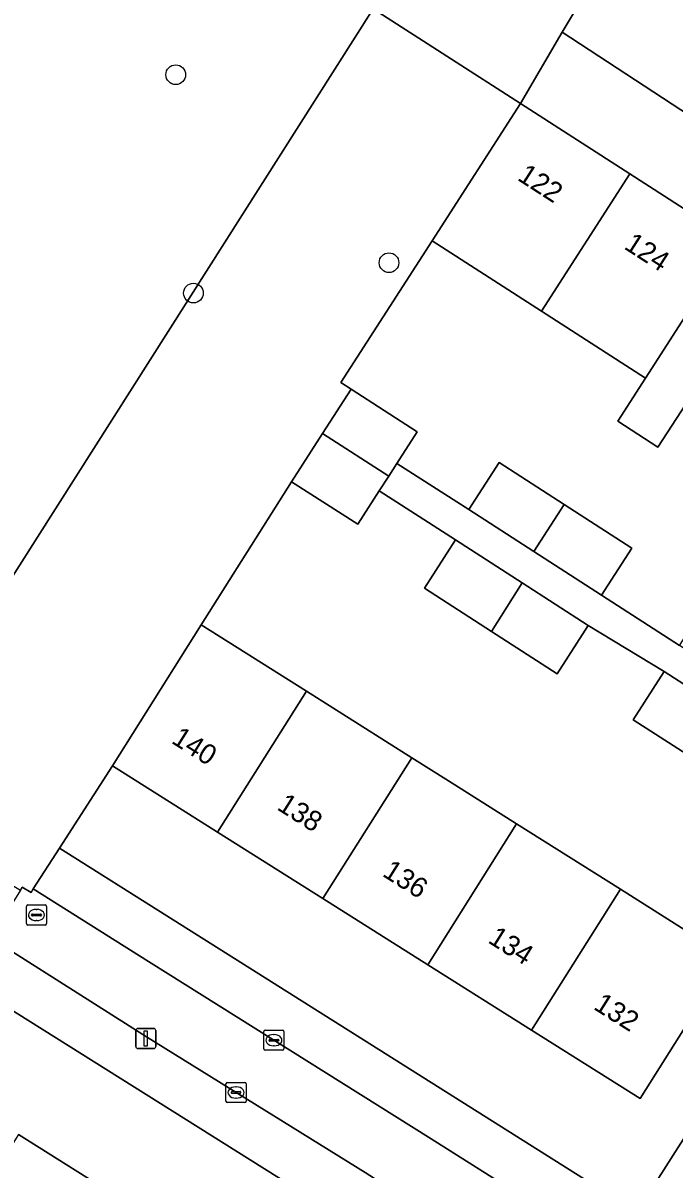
# Model space of a CAD drawing. Extents: x 159039 to 160102, y 381214 to 382524.
# Drawn here: x 159305.6 to 159337.9, y 381849 to 381905.9 of the extents above; entities that cross this region are included whole.
import ezdxf

# ---------------------------------------------------------------- set-up
doc = ezdxf.new("R2010")
doc.units = 0
for name, color, linetype in [('IMGEO_Boom', 7, 'Continuous'), ('IMGEO_Erf', 7, 'Continuous'), ('IMGEO_Groenvoorziening', 7, 'Continuous'), ('IMGEO_Kolk', 7, 'Continuous'), ('IMGEO_Lichtmast', 7, 'Continuous'), ('IMGEO_Pand', 7, 'Continuous'), ('IMGEO_Pand_nummerreeks', 7, 'Continuous'), ('IMGEO_Rijbaan_lokaal_open', 7, 'Continuous'), ('IMGEO_Rioolput', 7, 'Continuous'), ('IMGEO_Voetpad_open', 7, 'Continuous')]:
    doc.layers.add(name, color=color, linetype=linetype)

msp = doc.modelspace()

# ---------------------------------------------------------------- linework, layer by layer
at = {"layer": 'IMGEO_Boom'}
for centre in [(159313.176, 381903.321), (159323.769, 381893.982), (159314.057, 381892.471)]:
    msp.add_circle(centre, 0.489, dxfattribs=at)
at = {"layer": 'IMGEO_Erf'}
for points in [[(159359.86, 381887.675), (159359.727, 381887.759), (159350.052, 381893.861), (159332.365, 381905.434), (159330.306, 381901.885), (159335.73, 381898.391), (159340.897, 381895.062), (159346.193, 381891.651), (159351.372, 381888.315), (159356.797, 381884.82), (159352.409, 381878.007), (159346.983, 381881.502), (159341.804, 381884.838), (159338.51, 381886.96)], [(159338.51, 381886.96), (159337.13, 381884.818), (159335.128, 381886.107), (159336.508, 381888.249), (159331.341, 381891.577), (159325.917, 381895.071), (159321.381, 381888.03), (159321.89, 381887.702), (159325.177, 381885.584), (159324.166, 381884.015), (159327.732, 381881.718), (159329.234, 381884.051), (159332.464, 381881.971), (159335.828, 381879.804), (159334.325, 381877.472), (159338.207, 381874.971), (159339.709, 381877.304), (159342.939, 381875.224), (159346.303, 381873.057), (159344.8, 381870.725), (159349.432, 381867.776), (159360.21, 381884.703)], [(159339.221, 381869.129), (159335.891, 381871.274), (159337.437, 381873.674), (159333.667, 381875.963), (159332.121, 381873.562), (159328.855, 381875.666), (159325.525, 381877.811), (159327.071, 381880.211), (159323.286, 381882.649), (159322.214, 381880.985), (159318.927, 381883.102), (159314.445, 381875.985), (159319.664, 381872.694), (159324.9, 381869.393), (159326.721, 381868.244), (159330.108, 381866.109), (159335.266, 381862.856), (159340.655, 381859.458), (159336.243, 381852.461), (159330.854, 381855.859), (159325.696, 381859.111), (159320.488, 381862.395), (159315.253, 381865.696), (159310.032, 381868.988), (159307.398, 381864.904), (159336.081, 381846.809), (159348.622, 381866.504)], [(159302.409, 381834.215), (159305.789, 381832.086), (159304.31, 381829.739), (159308.104, 381827.348), (159309.583, 381829.695), (159312.83, 381827.649), (159316.21, 381825.52), (159314.731, 381823.173), (159319.263, 381820.297), (159331.792, 381840.041), (159302.646, 381858.346)], [(159305.367, 381850.678), (159310.675, 381847.333), (159315.912, 381844.034), (159321.096, 381840.767), (159326.554, 381837.328), (159322.241, 381830.483), (159316.783, 381833.922), (159313.597, 381835.929), (159312.802, 381834.667), (159312.977, 381834.557), (159311.178, 381831.701), (159309.005, 381833.071), (159311.599, 381837.188), (159306.362, 381840.488), (159301.054, 381843.832)]]:
    msp.add_lwpolyline(points, dxfattribs=at)
at = {"layer": 'IMGEO_Groenvoorziening'}
for points in [[(159322.99, 381906.598), (159330.306, 381901.885), (159332.365, 381905.434), (159334.129, 381908.375), (159336.542, 381906.753)], [(159291.155, 381871.456), (159298.019, 381867.309), (159322.99, 381906.598)]]:
    msp.add_lwpolyline(points, dxfattribs=at)
msp.add_lwpolyline([(159318.927, 381883.102), (159320.467, 381885.492), (159321.89, 381887.702), (159321.381, 381888.03), (159325.917, 381895.071), (159330.306, 381901.885), (159322.99, 381906.598), (159298.019, 381867.309), (159305.459, 381862.815), (159305.548, 381862.956), (159305.988, 381862.692), (159306.102, 381862.87), (159307.398, 381864.904), (159310.032, 381868.988), (159314.445, 381875.985)], close=True, dxfattribs=at)
at = {"layer": 'IMGEO_Kolk'}
for p, q in [((159317.552, 381854.932), (159317.552, 381855.784)), ((159317.627, 381855.858), (159318.479, 381855.858)), ((159317.811, 381855.352), (159317.811, 381855.364)), ((159318.249, 381855.315), (159317.851, 381855.315)), ((159317.854, 381855.401), (159318.252, 381855.401)), ((159318.04, 381855.638), (159318.065, 381855.638)), ((159318.295, 381855.364), (159318.295, 381855.352)), ((159318.553, 381855.784), (159318.553, 381854.932)), ((159318.479, 381854.858), (159317.627, 381854.858)), ((159318.063, 381855.078), (159318.038, 381855.078)), ((159315.672, 381852.335), (159315.672, 381853.187)), ((159315.747, 381853.261), (159316.599, 381853.261)), ((159316.16, 381853.041), (159316.185, 381853.041)), ((159316.673, 381853.187), (159316.673, 381852.335)), ((159315.931, 381852.755), (159315.931, 381852.767)), ((159316.369, 381852.718), (159315.971, 381852.718)), ((159315.974, 381852.804), (159316.372, 381852.804)), ((159316.183, 381852.481), (159316.158, 381852.481)), ((159316.415, 381852.767), (159316.415, 381852.755)), ((159316.599, 381852.261), (159315.747, 381852.261))]:
    msp.add_line(p, q, dxfattribs=at)
for points in [[(159317.552, 381854.932), (159317.552, 381855.784)], [(159317.627, 381855.858), (159318.479, 381855.858)], [(159318.553, 381855.784), (159318.553, 381854.932)], [(159318.479, 381854.858), (159317.627, 381854.858)], [(159315.672, 381852.335), (159315.672, 381853.187)], [(159315.747, 381853.261), (159316.599, 381853.261)], [(159316.673, 381853.187), (159316.673, 381852.335)], [(159316.599, 381852.261), (159315.747, 381852.261)]]:
    msp.add_lwpolyline(points, dxfattribs=at)
for centre, radius, start, end in [((159317.629, 381855.782), 0.0765, 91.552, 178.448), ((159317.629, 381855.782), 0.0765, 91.552, 178.448), ((159317.851, 381855.361), 0.0403, 85.8775, 175.7526), ((159317.848, 381855.351), 0.0366, 178.938, 274.7102), ((159318.252, 381855.358), 0.043, 264.8664, 352.4533), ((159318.256, 381855.363), 0.0386, 1.7309, 96.639), ((159318.477, 381855.782), 0.0765, 1.552, 88.448), ((159318.477, 381855.782), 0.0765, 1.552, 88.448), ((159317.629, 381854.934), 0.0765, 181.552, 268.448), ((159317.629, 381854.934), 0.0765, 181.552, 268.448), ((159318.477, 381854.934), 0.0765, 271.552, 358.448), ((159318.477, 381854.934), 0.0765, 271.552, 358.448), ((159315.749, 381853.185), 0.0765, 91.552, 178.448), ((159315.749, 381853.185), 0.0765, 91.552, 178.448), ((159316.597, 381853.185), 0.0765, 1.552, 88.448), ((159316.597, 381853.185), 0.0765, 1.552, 88.448), ((159315.971, 381852.764), 0.0403, 85.8775, 175.7526), ((159315.968, 381852.754), 0.0366, 178.938, 274.7102), ((159316.372, 381852.761), 0.043, 264.8664, 352.4533), ((159316.376, 381852.766), 0.0386, 1.7309, 96.639), ((159315.749, 381852.337), 0.0765, 181.552, 268.448), ((159315.749, 381852.337), 0.0765, 181.552, 268.448), ((159316.597, 381852.337), 0.0765, 271.552, 358.448), ((159316.597, 381852.337), 0.0765, 271.552, 358.448)]:
    msp.add_arc(centre, radius, start, end, dxfattribs=at)
for centre, major_axis, ratio, start_param, end_param in [((159318.039, 381855.358), (-0.387, 0.002), 0.722429, 4.712389, 7.853982), ((159318.064, 381855.358), (-0.39, 0.002), 0.717154, 1.570796, 4.712389), ((159316.159, 381852.761), (-0.387, 0.002), 0.722429, 4.712389, 7.853982), ((159316.184, 381852.761), (-0.39, 0.002), 0.717154, 1.570796, 4.712389)]:
    msp.add_ellipse(centre, major_axis=major_axis, ratio=ratio, start_param=start_param, end_param=end_param, dxfattribs=at)
at = {"layer": 'IMGEO_Lichtmast'}
for p, q in [((159311.295, 381855.943), (159312.085, 381855.943)), ((159312.085, 381855.943), (159311.295, 381855.943)), ((159311.195, 381855.043), (159311.195, 381855.843)), ((159311.195, 381855.843), (159311.195, 381855.043)), ((159312.185, 381855.843), (159312.185, 381855.043)), ((159312.185, 381855.043), (159312.185, 381855.843)), ((159312.085, 381854.943), (159311.295, 381854.943)), ((159311.295, 381854.943), (159312.085, 381854.943))]:
    msp.add_line(p, q, dxfattribs=at)
msp.add_lwpolyline([(159311.615, 381855.818), (159311.765, 381855.818), (159311.765, 381855.068), (159311.615, 381855.068), (159311.615, 381855.818)], dxfattribs=at)
for centre, start, end in [((159311.295, 381855.843), 90, 180), ((159311.295, 381855.843), 90, 180), ((159312.085, 381855.843), 0, 90), ((159312.085, 381855.843), 360, 90), ((159311.295, 381855.043), 180, 270), ((159311.295, 381855.043), 180, 270), ((159312.085, 381855.043), 270, 0), ((159312.085, 381855.043), 270, 0)]:
    msp.add_arc(centre, 0.1, start, end, dxfattribs=at)
at = {"layer": 'IMGEO_Pand'}
for points in [[(159335.73, 381898.391), (159330.306, 381901.885), (159325.917, 381895.071), (159331.341, 381891.577)], [(159335.73, 381898.391), (159331.341, 381891.577), (159336.508, 381888.249), (159340.897, 381895.062)], [(159346.193, 381891.651), (159340.897, 381895.062), (159336.508, 381888.249), (159335.128, 381886.107), (159337.13, 381884.818), (159338.51, 381886.96), (159341.804, 381884.838)], [(159325.177, 381885.584), (159321.89, 381887.702), (159320.467, 381885.492), (159323.754, 381883.376), (159324.166, 381884.015)], [(159323.754, 381883.376), (159320.467, 381885.492), (159318.927, 381883.102), (159322.214, 381880.985), (159323.286, 381882.649)], [(159332.464, 381881.971), (159329.234, 381884.051), (159327.732, 381881.718), (159330.961, 381879.638)], [(159332.464, 381881.971), (159330.961, 381879.638), (159334.325, 381877.472), (159335.828, 381879.804)], [(159330.378, 381878.081), (159327.071, 381880.211), (159325.525, 381877.811), (159328.855, 381875.666)], [(159330.378, 381878.081), (159328.855, 381875.666), (159332.121, 381873.562), (159333.667, 381875.963)], [(159319.664, 381872.694), (159314.445, 381875.985), (159310.032, 381868.988), (159315.253, 381865.696)], [(159340.744, 381871.544), (159337.437, 381873.674), (159335.891, 381871.274), (159339.221, 381869.129)], [(159319.664, 381872.694), (159315.253, 381865.696), (159320.488, 381862.395), (159324.9, 381869.393)], [(159330.108, 381866.109), (159326.721, 381868.244), (159324.9, 381869.393), (159320.488, 381862.395), (159325.696, 381859.111)], [(159330.108, 381866.109), (159325.696, 381859.111), (159330.854, 381855.859), (159335.266, 381862.856)], [(159335.266, 381862.856), (159330.854, 381855.859), (159336.243, 381852.461), (159340.655, 381859.458)], [(159305.367, 381850.678), (159301.054, 381843.832), (159306.362, 381840.488), (159310.675, 381847.333)]]:
    msp.add_lwpolyline(points, close=True, dxfattribs=at)
at = {"layer": 'IMGEO_Rijbaan_lokaal_open'}
msp.add_lwpolyline([(159311.827, 381859.267), (159306.102, 381862.87), (159305.988, 381862.692), (159305.548, 381862.956), (159305.459, 381862.815), (159304.189, 381860.797), (159303.964, 381860.439), (159311.727, 381855.526), (159322.579, 381848.781), (159333.091, 381842.053), (159334.772, 381844.828), (159325.861, 381850.452)], close=True, dxfattribs=at)
at = {"layer": 'IMGEO_Rioolput'}
for p, q in [((159305.759, 381861.152), (159305.759, 381862.004)), ((159305.834, 381862.078), (159306.686, 381862.078)), ((159306.018, 381861.572), (159306.018, 381861.584)), ((159306.061, 381861.621), (159306.459, 381861.621)), ((159306.247, 381861.858), (159306.272, 381861.858)), ((159306.502, 381861.584), (159306.502, 381861.572)), ((159306.76, 381862.004), (159306.76, 381861.152)), ((159306.686, 381861.078), (159305.834, 381861.078)), ((159306.456, 381861.535), (159306.058, 381861.535)), ((159306.27, 381861.298), (159306.245, 381861.298))]:
    msp.add_line(p, q, dxfattribs=at)
for points in [[(159305.759, 381861.152), (159305.759, 381862.004)], [(159305.834, 381862.078), (159306.686, 381862.078)], [(159306.76, 381862.004), (159306.76, 381861.152)], [(159306.686, 381861.078), (159305.834, 381861.078)]]:
    msp.add_lwpolyline(points, dxfattribs=at)
for centre, radius, start, end in [((159305.836, 381862.002), 0.0765, 91.552, 178.448), ((159305.836, 381862.002), 0.0765, 91.552, 178.448), ((159306.058, 381861.581), 0.0403, 85.8775, 175.7526), ((159306.055, 381861.571), 0.0366, 178.938, 274.7102), ((159306.459, 381861.578), 0.043, 264.8664, 352.4533), ((159306.463, 381861.583), 0.0386, 1.7309, 96.639), ((159306.684, 381862.002), 0.0765, 1.552, 88.448), ((159306.684, 381862.002), 0.0765, 1.552, 88.448), ((159305.836, 381861.154), 0.0765, 181.552, 268.448), ((159305.836, 381861.154), 0.0765, 181.552, 268.448), ((159306.684, 381861.154), 0.0765, 271.552, 358.448), ((159306.684, 381861.154), 0.0765, 271.552, 358.448)]:
    msp.add_arc(centre, radius, start, end, dxfattribs=at)
for centre, major_axis, ratio, start_param, end_param in [((159306.246, 381861.578), (-0.387, 0.002), 0.722429, 4.712389, 7.853982), ((159306.271, 381861.578), (-0.39, 0.002), 0.717154, 1.570796, 4.712389)]:
    msp.add_ellipse(centre, major_axis=major_axis, ratio=ratio, start_param=start_param, end_param=end_param, dxfattribs=at)
at = {"layer": 'IMGEO_Voetpad_open'}
for points in [[(159336.542, 381906.753), (159334.129, 381908.375), (159332.365, 381905.434), (159350.052, 381893.861), (159359.727, 381887.759), (159359.86, 381887.675), (159363.058, 381885.654)], [(159360.21, 381884.703), (159349.432, 381867.776), (159348.622, 381866.504), (159336.081, 381846.809), (159334.772, 381844.828), (159333.091, 381842.053), (159331.792, 381840.041), (159319.263, 381820.297), (159318.408, 381818.949), (159308.582, 381803.464), (159307.369, 381801.54), (159304.374, 381796.799)]]:
    msp.add_lwpolyline(points, dxfattribs=at)
for points in [[(159334.325, 381877.472), (159330.961, 381879.638), (159327.732, 381881.718), (159324.166, 381884.015), (159323.754, 381883.376), (159323.286, 381882.649), (159327.071, 381880.211), (159330.378, 381878.081), (159333.667, 381875.963), (159337.437, 381873.674), (159340.744, 381871.544), (159344.033, 381869.426), (159348.622, 381866.504), (159349.432, 381867.776), (159344.8, 381870.725), (159341.436, 381872.891), (159338.207, 381874.971)], [(159307.398, 381864.904), (159306.102, 381862.87), (159311.827, 381859.267), (159325.861, 381850.452), (159334.772, 381844.828), (159336.081, 381846.809)], [(159311.727, 381855.526), (159303.964, 381860.439), (159302.646, 381858.346), (159331.792, 381840.041), (159333.091, 381842.053), (159322.579, 381848.781)]]:
    msp.add_lwpolyline(points, close=True, dxfattribs=at)

# ---------------------------------------------------------------- texts
at = {"layer": 'IMGEO_Pand_nummerreeks'}
for s, rotation, p in [('122', 327.2111, (159330.096, 381898.119)), ('124', 327.2111, (159335.395, 381894.705)), ('140', 327.7671, (159312.912, 381870.151)), ('138', 327.7671, (159318.154, 381866.846)), ('136', 327.7654, (159323.392, 381863.543)), ('134', 327.7671, (159328.635, 381860.237)), ('132', 327.7671, (159333.876, 381856.933))]:
    msp.add_text(s, height=1, rotation=rotation, dxfattribs=at).set_placement(p)

doc.saveas('drawing.dxf')
